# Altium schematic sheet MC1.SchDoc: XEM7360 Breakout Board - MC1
size C; Author: Nick Kettman; Organization: Opal Kelly; Address1: 13500 SW 72nd Ave Ste 100; Address2: Portland, OR 97223; Address4: http://www.opalkelly.com; DocumentNumber: xxx; Revision: 1; SheetNumber: 2; SheetTotal: 3; PageSetup: Record=PageOptions¦CenterHorizontal=True¦CenterVertical=True¦PrintScale=0.53¦XCorrection=1.00¦YCorrection=1.00¦PrintKind=0¦BorderSize=5000000¦LeftOffset=0¦BottomOffset=0¦Orientation=2¦PaperLength=1000¦PaperWidth=1000¦Scale=100¦PaperSource=7¦PrintQuality=-4¦MediaType=1¦DitherType=10¦PaperKind=Letter¦PrintScaleMode=1
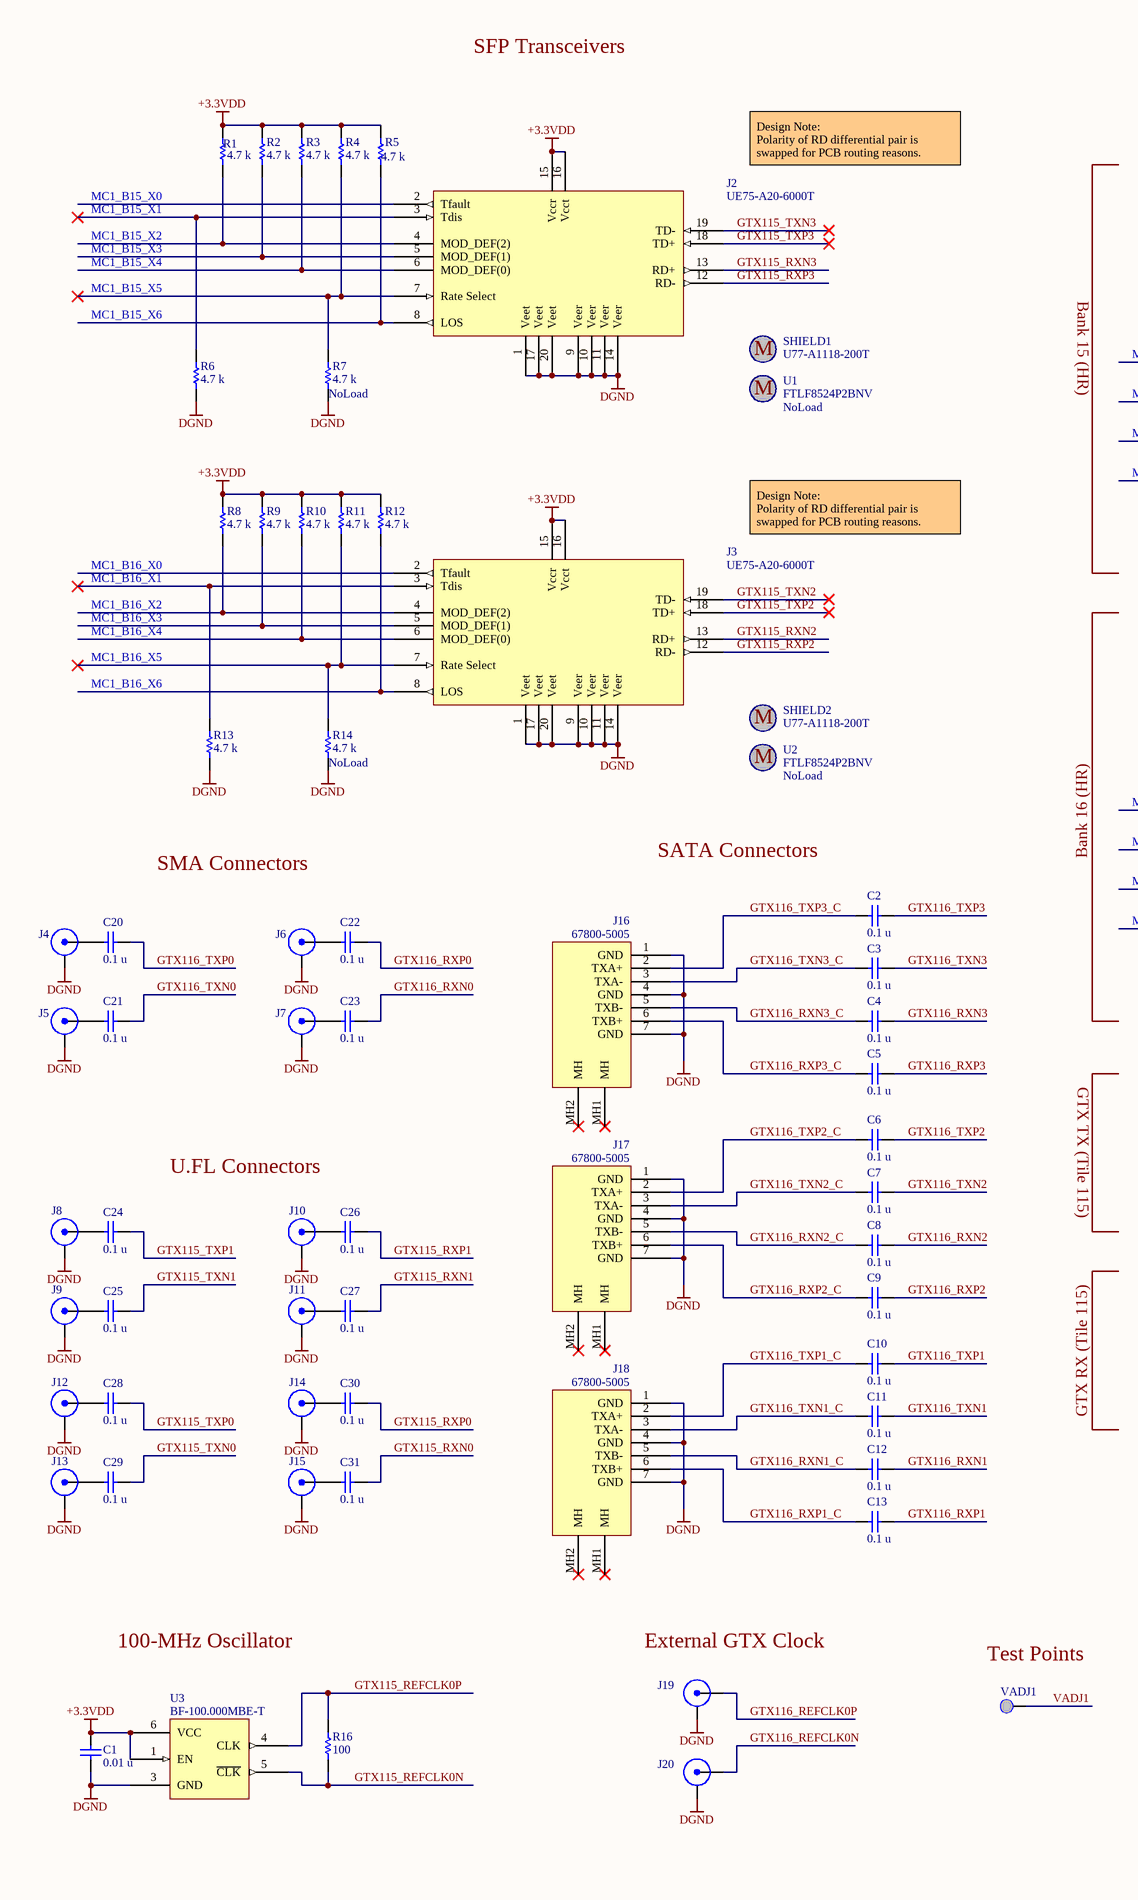
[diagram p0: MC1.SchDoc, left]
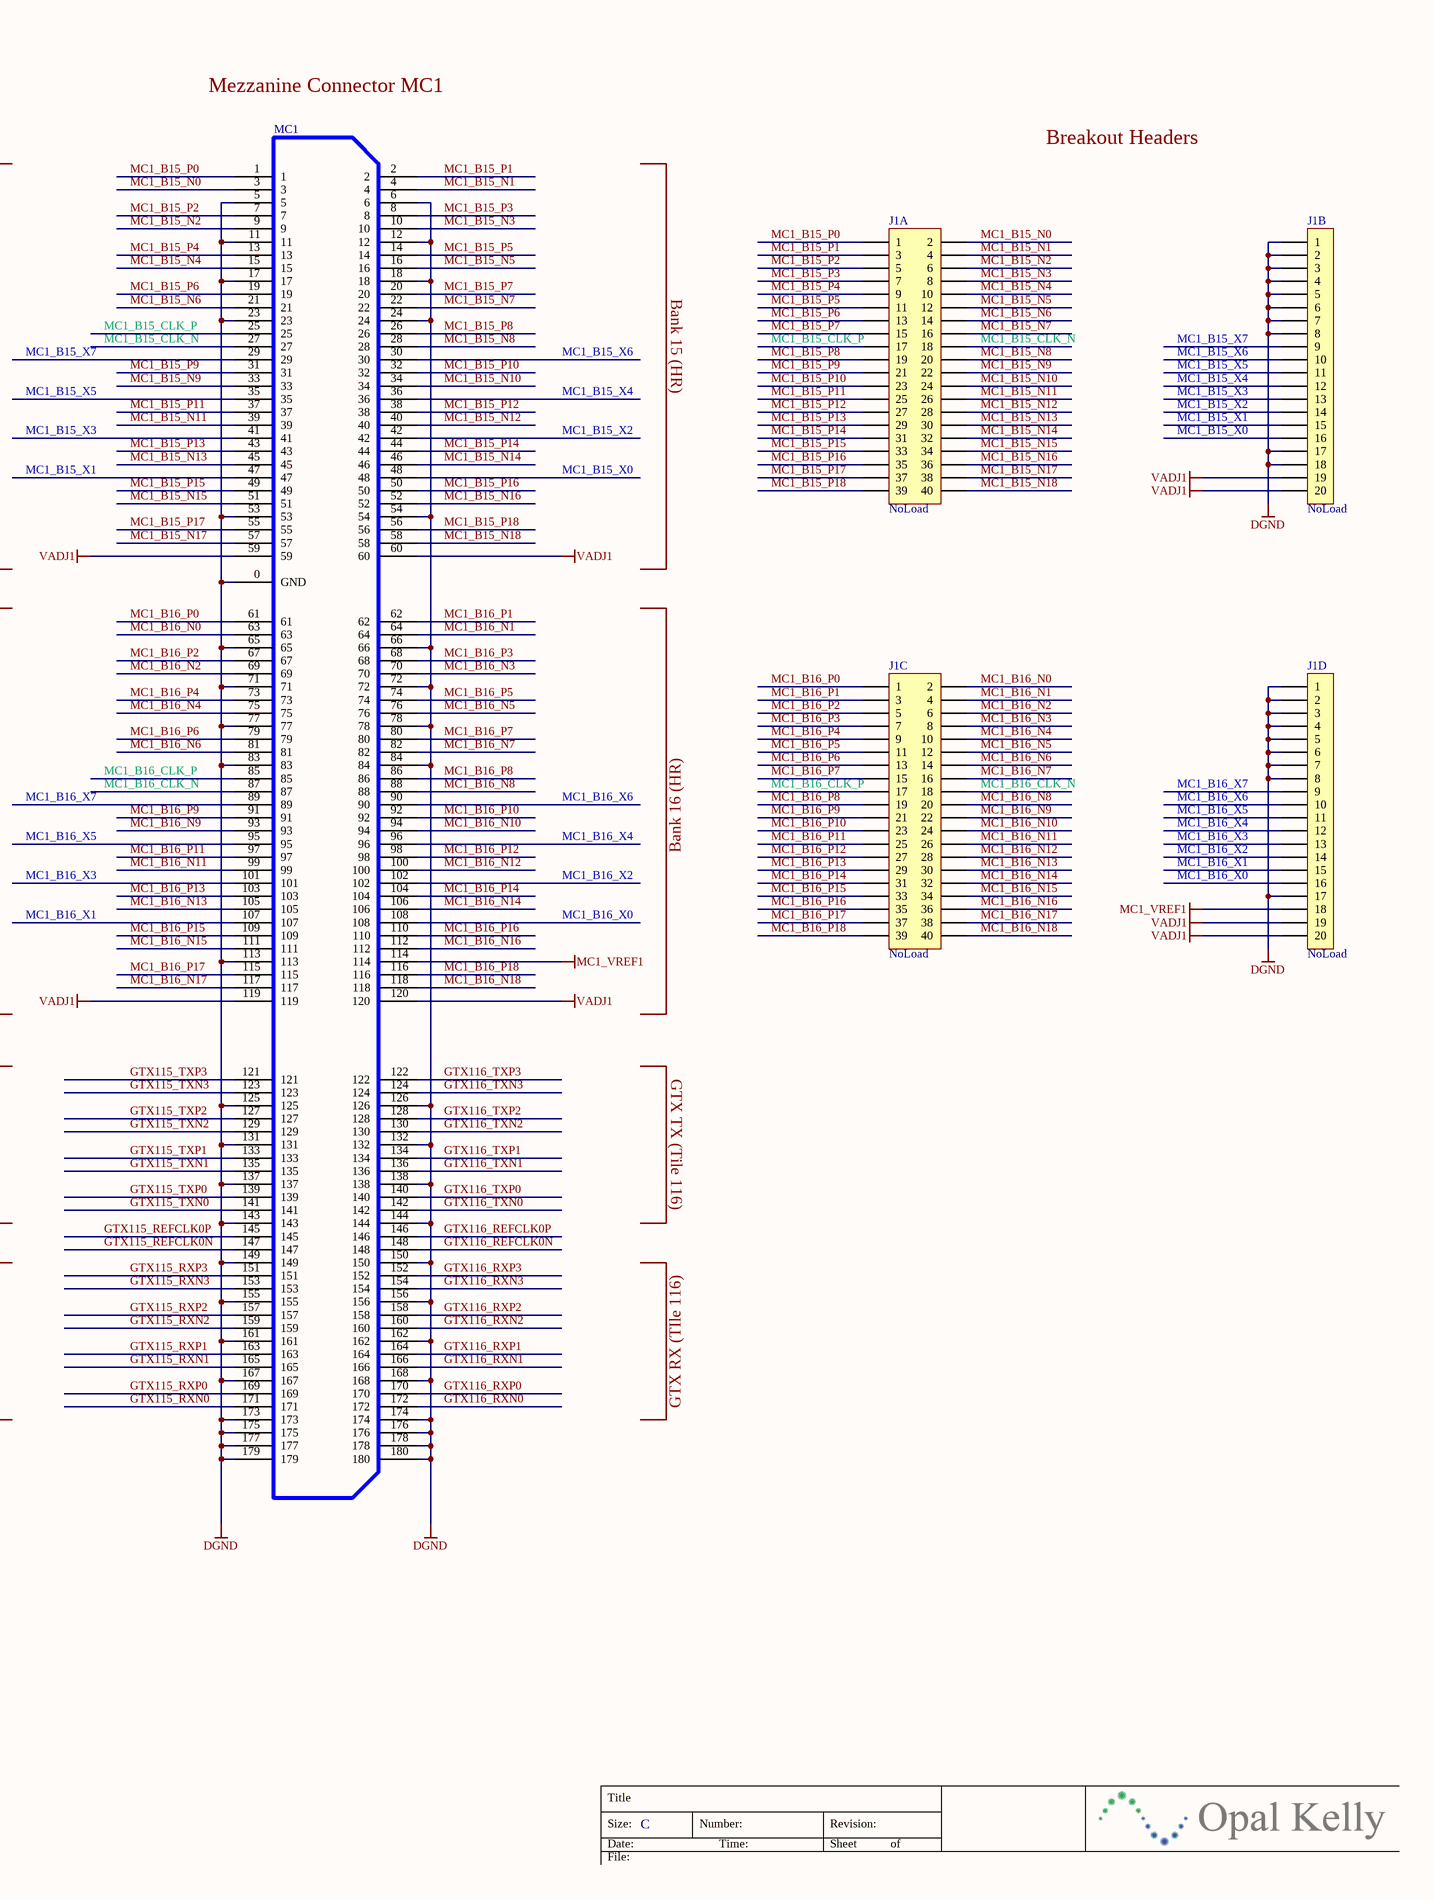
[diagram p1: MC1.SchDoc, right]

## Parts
C1  value 0.01 u  [CAPC1005N]  (hidden comment: C0402C103K4RACTU)
C2  value 0.1 u  [CAPC1005N]  (hidden comment: C0402C104K8PACTU)
C3  value 0.1 u  [CAPC1005N]  (hidden comment: C0402C104K8PACTU)
C4  value 0.1 u  [CAPC1005N]  (hidden comment: C0402C104K8PACTU)
C5  value 0.1 u  [CAPC1005N]  (hidden comment: C0402C104K8PACTU)
C6  value 0.1 u  [CAPC1005N]  (hidden comment: C0402C104K8PACTU)
C7  value 0.1 u  [CAPC1005N]  (hidden comment: C0402C104K8PACTU)
C8  value 0.1 u  [CAPC1005N]  (hidden comment: C0402C104K8PACTU)
C9  value 0.1 u  [CAPC1005N]  (hidden comment: C0402C104K8PACTU)
C10  value 0.1 u  [CAPC1005N]  (hidden comment: C0402C104K8PACTU)
C11  value 0.1 u  [CAPC1005N]  (hidden comment: C0402C104K8PACTU)
C12  value 0.1 u  [CAPC1005N]  (hidden comment: C0402C104K8PACTU)
C13  value 0.1 u  [CAPC1005N]  (hidden comment: C0402C104K8PACTU)
C20  value 0.1 u  [CAPC1005N]  (hidden comment: C0402C104K8PACTU)
C21  value 0.1 u  [CAPC1005N]  (hidden comment: C0402C104K8PACTU)
C22  value 0.1 u  [CAPC1005N]  (hidden comment: C0402C104K8PACTU)
C23  value 0.1 u  [CAPC1005N]  (hidden comment: C0402C104K8PACTU)
C24  value 0.1 u  [CAPC1005N]  (hidden comment: C0402C104K8PACTU)
C25  value 0.1 u  [CAPC1005N]  (hidden comment: C0402C104K8PACTU)
C26  value 0.1 u  [CAPC1005N]  (hidden comment: C0402C104K8PACTU)
C27  value 0.1 u  [CAPC1005N]  (hidden comment: C0402C104K8PACTU)
C28  value 0.1 u  [CAPC1005N]  (hidden comment: C0402C104K8PACTU)
C29  value 0.1 u  [CAPC1005N]  (hidden comment: C0402C104K8PACTU)
C30  value 0.1 u  [CAPC1005N]  (hidden comment: C0402C104K8PACTU)
C31  value 0.1 u  [CAPC1005N]  (hidden comment: C0402C104K8PACTU)
J1A  0877584016  [HDR2X20-2MM]  (value not drawn)
J1B  Header, 20-Pin, Single Row  [HDR1X20-2MM]  (value not drawn)
J1C  0877584016  [HDR2X20-2MM]  (value not drawn)
J1D  Header, 20-Pin, Single Row  [HDR1X20-2MM]  (value not drawn)
J2  UE75-A20-6000T  [SFP_RCPT_20_CAGE]
J3  UE75-A20-6000T  [SFP_RCPT_20_CAGE]
J4  TXP0  [SMA]  (value not drawn)
J5  TXN0  [SMA]  (value not drawn)
J6  RXP0  [SMA]  (value not drawn)
J7  RXN0  [SMA]  (value not drawn)
J8  TXP1  [UFL-R-SMT-1]  (value not drawn)
J9  TXN1  [UFL-R-SMT-1]  (value not drawn)
J10  RXP1  [UFL-R-SMT-1]  (value not drawn)
J11  RXN1  [UFL-R-SMT-1]  (value not drawn)
J12  TXP0  [UFL-R-SMT-1]  (value not drawn)
J13  TXN0  [UFL-R-SMT-1]  (value not drawn)
J14  RXP0  [UFL-R-SMT-1]  (value not drawn)
J15  RXN0  [UFL-R-SMT-1]  (value not drawn)
J16  67800-5005  [MOLEX-67800-5005]
J17  67800-5005  [MOLEX-67800-5005]
J18  67800-5005  [MOLEX-67800-5005]
J19  901-144-8RFX  [SMA]  (value not drawn)
J20  901-144-8RFX  [SMA]  (value not drawn)
MC1  QTH-090-01-F-D-A  [QTH-090-01-X-D]  (value not drawn)
R1  value 4.7 k  [RESC1005N]  (hidden comment: CRCW04024K70JNED)
R2  value 4.7 k  [RESC1005N]  (hidden comment: CRCW04024K70JNED)
R3  value 4.7 k  [RESC1005N]  (hidden comment: CRCW04024K70JNED)
R4  value 4.7 k  [RESC1005N]  (hidden comment: CRCW04024K70JNED)
R5  value 4.7 k  [RESC1005N]  (hidden comment: CRCW04024K70JNED)
R6  value 4.7 k  [RESC1005N]  (hidden comment: CRCW04024K70JNED)
R7  value 4.7 k  [RESC1005N]  (hidden comment: CRCW04024K70JNED)
R8  value 4.7 k  [RESC1005N]  (hidden comment: CRCW04024K70JNED)
R9  value 4.7 k  [RESC1005N]  (hidden comment: CRCW04024K70JNED)
R10  value 4.7 k  [RESC1005N]  (hidden comment: CRCW04024K70JNED)
R11  value 4.7 k  [RESC1005N]  (hidden comment: CRCW04024K70JNED)
R12  value 4.7 k  [RESC1005N]  (hidden comment: CRCW04024K70JNED)
R13  value 4.7 k  [RESC1005N]  (hidden comment: CRCW04024K70JNED)
R14  value 4.7 k  [RESC1005N]  (hidden comment: CRCW04024K70JNED)
R16  value 100  [RESC1608N]  (hidden comment: CRCW0603100RFKEA)
SHIELD1  U77-A1118-200T  (mechanical)
SHIELD2  U77-A1118-200T  (mechanical)
TP1  VADJ1  [TP_MED]
U1  FTLF8524P2BNV  (mechanical)
U2  FTLF8524P2BNV  (mechanical)
U3  BF-100.000MBE-T  [OSC_SMD6_5x7]

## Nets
+3.3VDD: C1.2 J2.15(Vccr) J2.16(Vcct) J3.15(Vccr) J3.16(Vcct) R1.2 R2.2 R3.2 R4.2 R5.2 R8.1 R9.1 R10.1 R11.1 R12.1 U3.1(EN) U3.6(VCC)
DGND: C1.1 J1B.1 J1B.2 J1B.3 J1B.4 J1B.5 J1B.6 J1B.7 J1B.8 J1B.17 J1B.18 J1D.1 J1D.2 J1D.3 J1D.4 J1D.5 J1D.6 J1D.7 J1D.8 J1D.17 J2.1(Veet) J2.9(Veer) J2.10(Veer) J2.11(Veer) J2.14(Veer) J2.17(Veet) J2.20(Veet) J3.1(Veet) J3.9(Veer) J3.10(Veer) J3.11(Veer) J3.14(Veer) J3.17(Veet) J3.20(Veet) J4.2(GND) J5.2(GND) J6.2(GND) J7.2(GND) J8.2(GND) J9.2(GND) J10.2(GND) J11.2(GND) J12.2(GND) J13.2(GND) J14.2(GND) J15.2(GND) J16.1(GND) J16.4(GND) J16.7(GND) J17.1(GND) J17.4(GND) J17.7(GND) J18.1(GND) J18.4(GND) J18.7(GND) J19.2(GND) J20.2(GND) MC1.0(GND) MC1.5 MC1.6 MC1.11 MC1.12 MC1.17 MC1.18 MC1.23 MC1.24 MC1.53 MC1.54 MC1.65 MC1.66 MC1.71 MC1.72 MC1.77 MC1.78 MC1.83 MC1.84 MC1.113 MC1.125 MC1.126 MC1.131 MC1.132 MC1.137 MC1.138 MC1.143 MC1.144 MC1.149 MC1.150 MC1.155 MC1.156 MC1.161 MC1.162 MC1.167 MC1.168 MC1.173 MC1.174 MC1.175 MC1.176 MC1.177 MC1.178 MC1.179 MC1.180 R6.2 R7.2 R13.2 R14.2 U3.3(GND)
MC1_VREF1: J1D.18 MC1.114
VADJ1: J1B.19 J1B.20 J1D.19 J1D.20 MC1.59 MC1.60 MC1.119 MC1.120 TP1.1(PIN)
GTX115_REFCLK0N: MC1.147 R16.1 U3.5(~{CLK})
GTX115_REFCLK0P: MC1.145 R16.2 U3.4(CLK)
GTX115_RXN0: C31.2 MC1.171
GTX115_RXN1: C27.2 MC1.165
GTX115_RXN2: J3.13(RD+) MC1.159
GTX115_RXN3: J2.13(RD+) MC1.153
GTX115_RXP0: C30.2 MC1.169
GTX115_RXP1: C26.2 MC1.163
GTX115_RXP2: J3.12(RD-) MC1.157
GTX115_RXP3: J2.12(RD-) MC1.151
GTX115_TXN0: C29.2 MC1.141
GTX115_TXN1: C25.2 MC1.135
GTX115_TXN2: J3.19(TD-) MC1.129
GTX115_TXN3: J2.19(TD-) MC1.123
GTX115_TXP0: C28.2 MC1.139
GTX115_TXP1: C24.2 MC1.133
GTX115_TXP2: J3.18(TD+) MC1.127
GTX115_TXP3: J2.18(TD+) MC1.121
GTX116_REFCLK0N: J20.1(SIGNAL) MC1.148
GTX116_REFCLK0P: J19.1(SIGNAL) MC1.146
GTX116_RXN0: C23.2 MC1.172
GTX116_RXN1: C12.2 MC1.166
GTX116_RXN1_C: C12.1 J18.5(TXB-)
GTX116_RXN2: C8.2 MC1.160
GTX116_RXN2_C: C8.1 J17.5(TXB-)
GTX116_RXN3: C4.2 MC1.154
GTX116_RXN3_C: C4.1 J16.5(TXB-)
GTX116_RXP0: C22.2 MC1.170
GTX116_RXP1: C13.2 MC1.164
GTX116_RXP1_C: C13.1 J18.6(TXB+)
GTX116_RXP2: C9.2 MC1.158
GTX116_RXP2_C: C9.1 J17.6(TXB+)
GTX116_RXP3: C5.2 MC1.152
GTX116_RXP3_C: C5.1 J16.6(TXB+)
GTX116_TXN0: C21.2 MC1.142
GTX116_TXN1: C11.2 MC1.136
GTX116_TXN1_C: C11.1 J18.3(TXA-)
GTX116_TXN2: C7.2 MC1.130
GTX116_TXN2_C: C7.1 J17.3(TXA-)
GTX116_TXN3: C3.2 MC1.124
GTX116_TXN3_C: C3.1 J16.3(TXA-)
GTX116_TXP0: C20.2 MC1.140
GTX116_TXP1: C10.2 MC1.134
GTX116_TXP1_C: C10.1 J18.2(TXA+)
GTX116_TXP2: C6.2 MC1.128
GTX116_TXP2_C: C6.1 J17.2(TXA+)
GTX116_TXP3: C2.2 MC1.122
GTX116_TXP3_C: C2.1 J16.2(TXA+)
MC1_B15_CLK_N: J1A.18 MC1.27
MC1_B15_CLK_P: J1A.17 MC1.25
MC1_B15_N0: J1A.2 MC1.3
MC1_B15_N1: J1A.4 MC1.4
MC1_B15_N2: J1A.6 MC1.9
MC1_B15_N3: J1A.8 MC1.10
MC1_B15_N4: J1A.10 MC1.15
MC1_B15_N5: J1A.12 MC1.16
MC1_B15_N6: J1A.14 MC1.21
MC1_B15_N7: J1A.16 MC1.22
MC1_B15_N8: J1A.20 MC1.28
MC1_B15_N9: J1A.22 MC1.33
MC1_B15_N10: J1A.24 MC1.34
MC1_B15_N11: J1A.26 MC1.39
MC1_B15_N12: J1A.28 MC1.40
MC1_B15_N13: J1A.30 MC1.45
MC1_B15_N14: J1A.32 MC1.46
MC1_B15_N15: J1A.34 MC1.51
MC1_B15_N16: J1A.36 MC1.52
MC1_B15_N17: J1A.38 MC1.57
MC1_B15_N18: J1A.40 MC1.58
MC1_B15_P0: J1A.1 MC1.1
MC1_B15_P1: J1A.3 MC1.2
MC1_B15_P2: J1A.5 MC1.7
MC1_B15_P3: J1A.7 MC1.8
MC1_B15_P4: J1A.9 MC1.13
MC1_B15_P5: J1A.11 MC1.14
MC1_B15_P6: J1A.13 MC1.19
MC1_B15_P7: J1A.15 MC1.20
MC1_B15_P8: J1A.19 MC1.26
MC1_B15_P9: J1A.21 MC1.31
MC1_B15_P10: J1A.23 MC1.32
MC1_B15_P11: J1A.25 MC1.37
MC1_B15_P12: J1A.27 MC1.38
MC1_B15_P13: J1A.29 MC1.43
MC1_B15_P14: J1A.31 MC1.44
MC1_B15_P15: J1A.33 MC1.49
MC1_B15_P16: J1A.35 MC1.50
MC1_B15_P17: J1A.37 MC1.55
MC1_B15_P18: J1A.39 MC1.56
MC1_B15_X0: J1B.16 J2.2(Tfault) MC1.48
MC1_B15_X1: J1B.15 J2.3(Tdis) MC1.47 R6.1
MC1_B15_X2: J1B.14 J2.4(MOD_DEF(2)) MC1.42 R1.1
MC1_B15_X3: J1B.13 J2.5(MOD_DEF(1)) MC1.41 R2.1
MC1_B15_X4: J1B.12 J2.6(MOD_DEF(0)) MC1.36 R3.1
MC1_B15_X5: J1B.11 J2.7(Rate_Select) MC1.35 R4.1 R7.1
MC1_B15_X6: J1B.10 J2.8(LOS) MC1.30 R5.1
MC1_B15_X7: J1B.9 MC1.29
MC1_B16_CLK_N: J1C.18 MC1.87
MC1_B16_CLK_P: J1C.17 MC1.85
MC1_B16_N0: J1C.2 MC1.63
MC1_B16_N1: J1C.4 MC1.64
MC1_B16_N2: J1C.6 MC1.69
MC1_B16_N3: J1C.8 MC1.70
MC1_B16_N4: J1C.10 MC1.75
MC1_B16_N5: J1C.12 MC1.76
MC1_B16_N6: J1C.14 MC1.81
MC1_B16_N7: J1C.16 MC1.82
MC1_B16_N8: J1C.20 MC1.88
MC1_B16_N9: J1C.22 MC1.93
MC1_B16_N10: J1C.24 MC1.94
MC1_B16_N11: J1C.26 MC1.99
MC1_B16_N12: J1C.28 MC1.100
MC1_B16_N13: J1C.30 MC1.105
MC1_B16_N14: J1C.32 MC1.106
MC1_B16_N15: J1C.34 MC1.111
MC1_B16_N16: J1C.36 MC1.112
MC1_B16_N17: J1C.38 MC1.117
MC1_B16_N18: J1C.40 MC1.118
MC1_B16_P0: J1C.1 MC1.61
MC1_B16_P1: J1C.3 MC1.62
MC1_B16_P2: J1C.5 MC1.67
MC1_B16_P3: J1C.7 MC1.68
MC1_B16_P4: J1C.9 MC1.73
MC1_B16_P5: J1C.11 MC1.74
MC1_B16_P6: J1C.13 MC1.79
MC1_B16_P7: J1C.15 MC1.80
MC1_B16_P8: J1C.19 MC1.86
MC1_B16_P9: J1C.21 MC1.91
MC1_B16_P10: J1C.23 MC1.92
MC1_B16_P11: J1C.25 MC1.97
MC1_B16_P12: J1C.27 MC1.98
MC1_B16_P13: J1C.29 MC1.103
MC1_B16_P14: J1C.31 MC1.104
MC1_B16_P15: J1C.33 MC1.109
MC1_B16_P16: J1C.35 MC1.110
MC1_B16_P17: J1C.37 MC1.115
MC1_B16_P18: J1C.39 MC1.116
MC1_B16_X0: J1D.16 J3.2(Tfault) MC1.108
MC1_B16_X1: J1D.15 J3.3(Tdis) MC1.107 R13.1
MC1_B16_X2: J1D.14 J3.4(MOD_DEF(2)) MC1.102 R8.2
MC1_B16_X3: J1D.13 J3.5(MOD_DEF(1)) MC1.101 R9.2
MC1_B16_X4: J1D.12 J3.6(MOD_DEF(0)) MC1.96 R10.2
MC1_B16_X5: J1D.11 J3.7(Rate_Select) MC1.95 R11.2 R14.1
MC1_B16_X6: J1D.10 J3.8(LOS) MC1.90 R12.2
MC1_B16_X7: J1D.9 MC1.89
NetC20_1: C20.1 J4.1(SIGNAL)
NetC21_1: C21.1 J5.1(SIGNAL)
NetC22_1: C22.1 J6.1(SIGNAL)
NetC23_1: C23.1 J7.1(SIGNAL)
NetC24_1: C24.1 J8.1(SIGNAL)
NetC25_1: C25.1 J9.1(SIGNAL)
NetC26_1: C26.1 J10.1(SIGNAL)
NetC27_1: C27.1 J11.1(SIGNAL)
NetC28_1: C28.1 J12.1(SIGNAL)
NetC29_1: C29.1 J13.1(SIGNAL)
NetC30_1: C30.1 J14.1(SIGNAL)
NetC31_1: C31.1 J15.1(SIGNAL)

Not connected (* = marked no-connect by the designer): J16 MH1(MH)* MH2(MH)*; J17 MH1(MH)* MH2(MH)*; J18 MH1(MH)* MH2(MH)*

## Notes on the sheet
- SFP Transceivers
- Mezzanine Connector MC1
- Design Note:
  Polarity of RD differential pair is swapped for PCB routing reasons.
- Breakout Headers
- Bank 15 (HR)
- Bank 16 (HR)
- SMA Connectors
- SATA Connectors
- GTX TX (Tile 115)
- GTX TX (Tile 116)
- U.FL Connectors
- GTX RX (Tile 115)
- GTX RX (TIle 116)
- 100-MHz Oscillator
- (near J19) External GTX Clock
- (near TP1) Test Points
- Title
- Size:
- Date:
- File:
- C
- Number:
- Time:
- Revision:
- Sheet
- of

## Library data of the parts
C1 = 000295: Ceramic Capacitor; Manufacturer: Kemet; partnumber: 000295; Description 2: SM-0402, 10%, 6.3V, X5R; ValueFloat: 1E-8; Tolerance (%): 10
C2-C13 C20-C31 = 000070: Ceramic capacitor; Manufacturer: Kemet; partnumber: 000070; Description 2: SM-0402, 10%, 10v; ValueFloat: 1E-7; Tolerance (%): 10
J1A J1C = 000583: 2mm header, 20x2, thru-hole; Manufacturer: Molex; partnumber: 000583
J1B J1D = 001334: 2mm header, 20x1, thru-hole; PartNumber: 001334; Manufacturer: 3M; Manufacturer_PN: 951120-8622-AR; x_lifecycle_status: Production
J2 J3 = 000986: SFP 20-POS Recepticle; Manufacturer: Amphenol; partnumber: 000986; Description 2: Right Angle, SMD, 15AU Gold
J4-J7 = 000974: Straight SMA PCB Mount; Manufacturer: Amphenol; Manufacturer_PN: 901-144-8RFX; partnumber: 000974
J8-J15 = 001335: U.FL surface-mount coaxial connector; Manufacturer: Hirose; Manufacturer_PN: U.FL-R-SMT-1; partnumber: 001335; x_lifecycle_status: Production
J16-J18 = 000988: SATA 7-pin receptacle; Manufacturer: Molex; partnumber: 000988; Description 2: Vertical Mount, SMD, Latch, 15u Gold; x_lifecycle_status: Production
J19 J20 = 000974: Straight SMA PCB Mount; Manufacturer: Amphenol; partnumber: 000974
MC1 = 000876: 0.5mm hi-speed, high-density header (Female); Manufacturer: Samtec; partnumber: 000876; Description 2: 180-pin, ground plane in middle
R1-R14 = 000754: Thick-film resistor; Manufacturer: Vishay; partnumber: 000754; Description 2: SM-0402, 5%, 1/16W; ValueFloat: 4700; Tolerance (%): 5
R16 = 000789: Thick-film resistor; Manufacturer: Vishay; partnumber: 000789; Description 2: SM-0603, 1%, 1/10W; Tolerance (%): 1
SHIELD1 SHIELD2 = 000987: SFP Single Cage; Manufacturer: Amphenol; partnumber: 000987; Description 2: Pressfit; x_lifecycle_status: Production
TP1 = 000265: Testpoint; Manufacturer: Keystone Electronics; Manufacturer_PN: 5007; partnumber: 000265; Description 2: 0.063 in. diameter, compact, White
U1 U2 = 000985: SFP Transceiver; Manufacturer: Finisar; partnumber: 000985; Description 2: 4.25Gb/s, Narrow Extraction Bail, Rate Selectable
U3 = 000846: 100 MHz LVDS oscillator; Manufacturer: TXC Corporation; partnumber: 000846; Description 2: 3.3v, 50ppm, industrial temp, 7mm x 5mm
